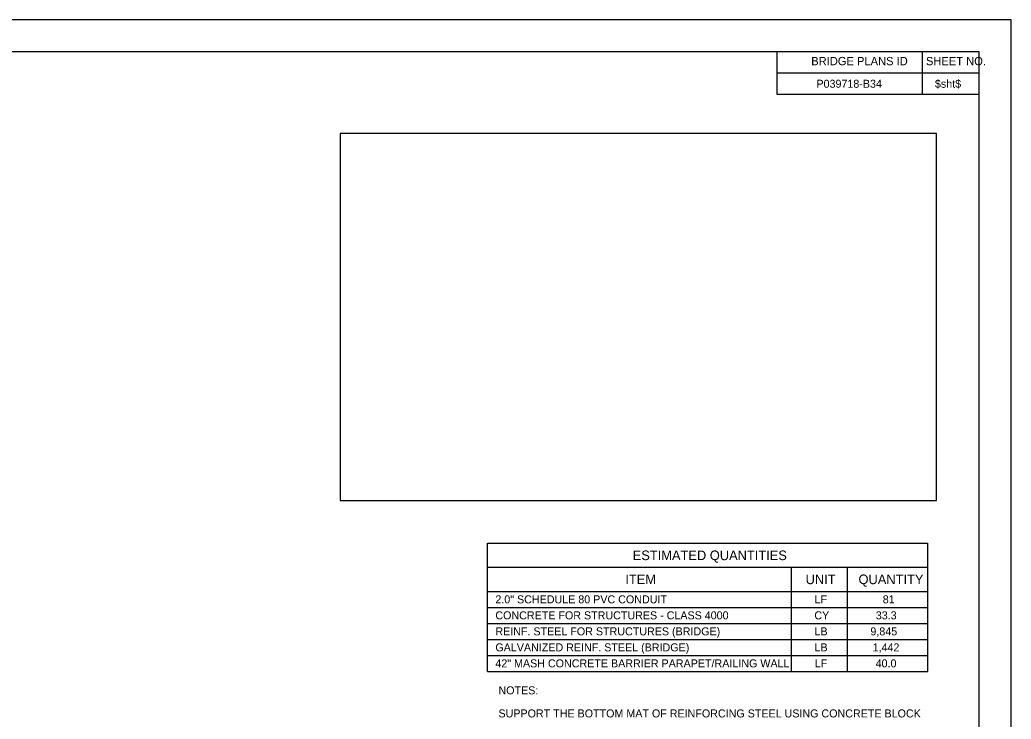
# Model space of a CAD drawing. Extents: x 2799.7 to 2896, y 515.2 to 573.9.
# Drawn here: x 2854.42 to 2895.69, y 544.77 to 573.89 of the extents above; entities that cross this region are included whole.
import ezdxf

# ---------------------------------------------------------------- set-up
doc = ezdxf.new("R2010")
doc.units = 0
for name, color, linetype in [('BR_AUTO DIMENSION', 7, 'Continuous'), ('BR_BORDER LINES', 7, 'Continuous'), ('BR_TABLE LINES', 7, 'Continuous'), ('BR_TEXT', 7, 'Continuous'), ('Level 31', 7, 'Continuous')]:
    doc.layers.add(name, color=color, linetype=linetype)

msp = doc.modelspace()

# ---------------------------------------------------------------- linework, layer by layer
at = {"layer": 'BR_AUTO DIMENSION'}
msp.add_lwpolyline([(2867.756, 553.871), (2892.582, 553.871), (2892.582, 569.155), (2867.756, 569.155)], close=True, dxfattribs=at)
at = {"layer": 'BR_BORDER LINES'}
for p, q in [((2894.359, 572.556), (2804.582, 572.556)), ((2885.953, 570.779), (2885.953, 572.556)), ((2891.996, 570.779), (2891.996, 572.556)), ((2894.359, 516.556), (2894.359, 572.556)), ((2885.953, 571.678), (2894.359, 571.678)), ((2891.996, 571.678), (2894.359, 571.678)), ((2894.359, 570.779), (2885.953, 570.779))]:
    msp.add_line(p, q, dxfattribs=at)
at = {"layer": 'BR_TABLE LINES'}
for p, q in [((2873.885, 546.758), (2873.885, 552.091)), ((2873.885, 552.091), (2892.214, 552.091)), ((2892.219, 546.758), (2892.219, 552.091)), ((2873.89, 551.091), (2892.219, 551.091)), ((2886.552, 546.758), (2886.552, 551.091)), ((2888.886, 546.758), (2888.886, 551.091)), ((2873.89, 550.091), (2892.219, 550.091)), ((2873.89, 549.425), (2892.219, 549.425)), ((2873.89, 548.758), (2892.219, 548.758)), ((2873.89, 548.091), (2892.219, 548.091)), ((2873.89, 547.425), (2892.219, 547.425)), ((2873.885, 546.758), (2892.219, 546.758))]:
    msp.add_line(p, q, dxfattribs=at)
at = {"layer": 'Level 31'}
msp.add_line((2895.694, 573.89), (2799.693, 573.89), dxfattribs=at)
msp.add_lwpolyline([(2799.693, 573.89), (2799.693, 515.223), (2895.694, 515.223), (2895.694, 573.89)], dxfattribs=at)

# ---------------------------------------------------------------- texts
at = {"layer": 'BR_TEXT'}
for s, height, p in [('BRIDGE PLANS ID', 0.34667, (2887.369, 571.998)), ('SHEET NO.', 0.3467, (2892.145, 571.998)), ('P039718-B34', 0.33334, (2887.586, 571.061)), ('$sht$', 0.3333, (2892.519, 571.061)), ('ESTIMATED QUANTITIES', 0.40001, (2879.937, 551.391)), ('ITEM', 0.4, (2879.63, 550.391)), ('UNIT', 0.4, (2887.136, 550.391)), ('QUANTITY', 0.4, (2889.338, 550.391)), ('2.0" SCHEDULE 80 PVC CONDUIT', 0.33334, (2874.219, 549.591)), ('LF', 0.3333, (2887.509, 549.591)), ('81', 0.3333, (2890.347, 549.591)), ('CONCRETE FOR STRUCTURES - CLASS 4000', 0.33334, (2874.219, 548.925)), ('CY', 0.3333, (2887.5, 548.925)), ('33.3', 0.3333, (2890.058, 548.925)), ('REINF. STEEL FOR STRUCTURES (BRIDGE)', 0.33334, (2874.219, 548.258)), ('LB', 0.3333, (2887.505, 548.258)), ('9,845', 0.3333, (2889.833, 548.258)), ('GALVANIZED REINF. STEEL (BRIDGE)', 0.33334, (2874.219, 547.591)), ('LB', 0.3333, (2887.507, 547.591)), ('1,442', 0.3333, (2889.925, 547.591)), ('42" MASH CONCRETE BARRIER PARAPET/RAILING WALL', 0.33334, (2874.219, 546.925)), ('LF', 0.3333, (2887.513, 546.925)), ('40.0', 0.3333, (2890.05, 546.925))]:
    msp.add_text(s, height=height, dxfattribs=at).set_placement(p)
for s, height, p in [('NOTES:', 0.3333, (2874.348, 545.802)), ('SUPPORT THE BOTTOM MAT OF REINFORCING STEEL USING CONCRETE BLOCK ', 0.33333, (2874.348, 544.841))]:
    msp.add_text(s, height=height, rotation=360, dxfattribs=at).set_placement(p)

doc.saveas('drawing.dxf')
